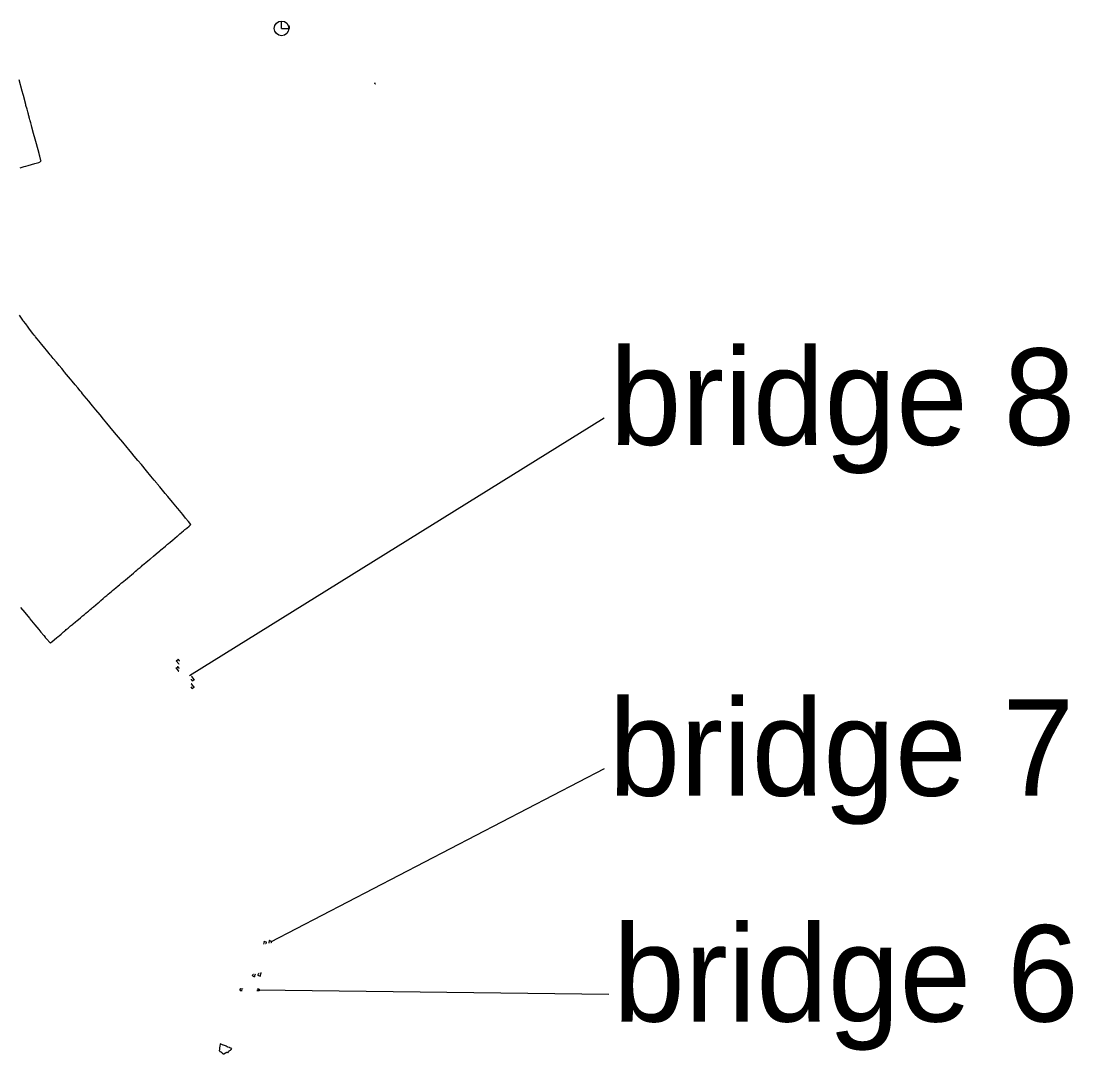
# Model space of a CAD drawing. Extents: x 620961 to 671816, y 407040 to 436930.
# Drawn here: x 648401 to 671816, y 407040 to 430021 of the extents above; entities that cross this region are included whole.
import ezdxf

# ---------------------------------------------------------------- set-up
doc = ezdxf.new("R2010")
doc.units = 0
for name, color, linetype in [('R_Lighting_Poles', 7, 'Continuous'), ('R_No Plot', 7, 'Continuous'), ('T_Lighting_Boxes', 7, 'Continuous'), ('T_Lighting_Conduit', 7, 'Continuous')]:
    doc.layers.add(name, color=color, linetype=linetype)

msp = doc.modelspace()

# ---------------------------------------------------------------- linework, layer by layer
at = {"layer": 'R_Lighting_Poles'}
for p, q in [((656273, 428641), (656271, 428643)), ((656279, 428634), (656273, 428641)), ((656274, 428636), (656273, 428634)), ((656274, 428636), (656278, 428639)), ((656278, 428639), (656280, 428641)), ((656288, 428625), (656279, 428634))]:
    msp.add_line(p, q, dxfattribs=at)
msp.add_circle((656289, 428623), 2.4, dxfattribs=at)
for centre, radius, start, end in [((656274, 428640), 1.27, 92.9915, 132.6308), ((656274, 428640), 1.27, 132.6308, 172.2701), ((656276, 428640), 3.45, 172.2701, 196.0657), ((656278, 428640), 5.94, 196.0657, 210.9299), ((656281, 428642), 9.57, 210.9299, 222.6308), ((656274, 428638), 3.45, 69.1958, 92.9915), ((656281, 428642), 9.57, 222.6308, 234.3317), ((656273, 428635), 5.94, 54.3317, 69.1958), ((656271, 428632), 9.57, 42.6308, 54.3317), ((656279, 428639), 5.94, 234.3317, 249.1958), ((656278, 428637), 3.45, 249.1958, 272.9915), ((656271, 428632), 9.57, 30.9299, 42.6308), ((656274, 428634), 5.94, 16.0657, 30.9299), ((656279, 428635), 1.27, 312.6308, 352.2701), ((656279, 428635), 1.27, 272.9915, 312.6308), ((656276, 428635), 3.45, 352.2701, 16.0657)]:
    msp.add_arc(centre, radius, start, end, dxfattribs=at)
at = {"layer": 'R_No Plot'}
for p, q in [((661381, 421189), (652154, 415453)), ((661381, 413383), (653955, 409528)), ((661482, 408359), (653677, 408462))]:
    msp.add_line(p, q, dxfattribs=at)
for points in [[(648378, 426758), (648469, 426782), (648506, 426793), (648561, 426809), (648710, 426848), (648798, 426872), (648845, 426906), (648843, 426920), (648818, 427013), (648818, 427013), (648818, 427013), (648810, 427040), (648810, 427040), (648810, 427040), (648802, 427071), (648802, 427072), (648802, 427072), (648780, 427152), (648780, 427152), (648780, 427152), (648765, 427207), (648744, 427286), (648715, 427391), (648681, 427518), (648641, 427662), (648632, 427694), (648616, 427755), (648603, 427804), (648602, 427809), (648598, 427823), (648591, 427849), (648588, 427859), (648585, 427871), (648582, 427883), (648581, 427887), (648574, 427913), (648568, 427935), (648568, 427936), (648568, 427936), (648566, 427941), (648563, 427953), (648560, 427964), (648556, 427980), (648552, 427994), (648550, 428000), (648541, 428032), (648534, 428059), (648510, 428144), (648505, 428164), (648452, 428363), (648452, 428364), (648452, 428364), (648445, 428388), (648445, 428388), (648445, 428389), (648424, 428464), (648357, 428712)], [(648389, 416974), (648484, 416861), (648586, 416736), (648600, 416719), (648711, 416587), (648798, 416482), (648843, 416426), (648909, 416348), (648936, 416316), (648941, 416309), (648974, 416271), (649040, 416192), (649053, 416185), (649054, 416184), (649092, 416216), (649192, 416298), (649228, 416329), (649246, 416344), (649291, 416382), (649346, 416428), (649365, 416444), (649369, 416447), (649379, 416456), (649390, 416464), (649408, 416480), (649427, 416496), (649449, 416515), (649463, 416526), (649480, 416541), (649505, 416562), (649544, 416595), (649562, 416610), (649615, 416655), (649650, 416684), (649678, 416708), (649723, 416745), (649768, 416784), (649803, 416812), (649843, 416847), (649879, 416876), (649900, 416895), (649939, 416927), (649966, 416951), (649994, 416974), (650015, 416991), (650114, 417074), (650138, 417095), (650177, 417131), (650226, 417173), (650267, 417207), (650311, 417242), (650338, 417267), (650380, 417301), (650415, 417330), (650439, 417349), (650514, 417414), (650565, 417455), (650593, 417479), (650639, 417519), (650675, 417547), (650690, 417561), (650724, 417589), (650768, 417626), (650822, 417671), (650859, 417702), (650902, 417738), (650927, 417759), (650950, 417779), (650980, 417804), (650995, 417817), (651011, 417830), (651053, 417866), (651068, 417878), (651079, 417887), (651107, 417912), (651144, 417942), (651180, 417972), (651188, 417979), (651250, 418031), (651267, 418045), (651273, 418051), (651281, 418058), (651349, 418115), (651410, 418169), (651491, 418234), (651507, 418248), (651553, 418286), (651570, 418300), (651614, 418338), (651631, 418353), (651649, 418367), (651662, 418379), (651685, 418398), (651719, 418426), (651811, 418503), (651822, 418513), (651878, 418560), (651888, 418568), (651898, 418577), (651936, 418609), (651967, 418636), (651982, 418649), (652018, 418679), (652050, 418706), (652071, 418723), (652090, 418739), (652141, 418783), (652173, 418809), (652181, 418823), (652131, 418884), (652064, 418964), (651999, 419044), (651891, 419174), (651881, 419186), (651769, 419320), (651669, 419440), (651608, 419513), (651520, 419622), (651488, 419659), (651432, 419727), (651421, 419740), (651366, 419806), (651291, 419896), (651195, 420011), (651080, 420152), (651003, 420244), (650922, 420342), (650870, 420404), (650803, 420485), (650762, 420535), (650663, 420652), (650570, 420766), (650529, 420816), (650446, 420914), (650314, 421074), (650238, 421164), (650160, 421260), (650069, 421369), (649994, 421460), (649964, 421495), (649907, 421564), (649808, 421684), (649771, 421728), (649743, 421762), (649719, 421790), (649663, 421858), (649603, 421929), (649536, 422011), (649500, 422056), (649371, 422211), (649361, 422224), (649306, 422290), (649248, 422359), (649189, 422430), (649119, 422515), (649095, 422544), (649072, 422572), (649049, 422598), (649025, 422627), (648967, 422698), (648930, 422742), (648861, 422824), (648827, 422867), (648802, 422898), (648751, 422960), (648725, 422993), (648713, 423008), (648692, 423034), (648657, 423078), (648574, 423185), (648558, 423208), (648504, 423281), (648459, 423342), (648444, 423362), (648440, 423367), (648410, 423408), (648365, 423474)]]:
    msp.add_lwpolyline(points, dxfattribs=at)
msp.add_lwpolyline([(652873, 407252), (652836, 407267), (652833, 407248), (652828, 407223), (652822, 407196), (652820, 407180), (652818, 407161), (652816, 407145), (652811, 407106), (652822, 407100), (652829, 407098), (652833, 407095), (652834, 407095), (652845, 407087), (652850, 407085), (652854, 407083), (652859, 407082), (652863, 407080), (652865, 407079), (652874, 407065), (652884, 407046), (652886, 407046), (652890, 407048), (652896, 407049), (652901, 407048), (652901, 407047), (652903, 407045), (652908, 407042), (652912, 407040), (652913, 407040), (652955, 407064), (652961, 407066), (652968, 407071), (652975, 407075), (652982, 407080), (652988, 407081), (652994, 407082), (652998, 407078), (653000, 407077), (653007, 407071), (653010, 407070), (653027, 407102), (653034, 407108), (653037, 407110), (653043, 407113), (653051, 407118), (653060, 407124), (653068, 407132), (653078, 407142), (653090, 407159), (653068, 407169), (653046, 407178), (653040, 407180), (653007, 407194), (652991, 407201), (652970, 407210), (652950, 407219), (652933, 407226), (652910, 407236), (652902, 407239)], close=True, dxfattribs=at)
at = {"layer": 'T_Lighting_Boxes'}
for p, q in [((651850, 415625), (651852, 415622)), ((651856, 415790), (651858, 415787)), ((651889, 415657), (651892, 415654)), ((651896, 415821), (651898, 415819)), ((652211, 415175), (652213, 415172)), ((652217, 415340), (652220, 415337)), ((652251, 415207), (652253, 415204)), ((652257, 415372), (652259, 415369)), ((653812, 409542), (653811, 409538)), ((653929, 409564), (653928, 409561)), ((653978, 409552), (653978, 409548)), ((653861, 409529), (653860, 409525)), ((653554, 408780), (653552, 408776)), ((653601, 408760), (653599, 408756)), ((653677, 408793), (653676, 408790)), ((653724, 408775), (653723, 408771)), ((653283, 408487), (653279, 408487)), ((653282, 408448), (653279, 408448)), ((653702, 408478), (653698, 408478)), ((653701, 408441), (653698, 408442))]:
    msp.add_line(p, q, dxfattribs=at)
for points in [[(651852, 415622), (651850, 415620), (651847, 415623), (651850, 415625)], [(651858, 415787), (651856, 415785), (651854, 415788), (651856, 415790)], [(651892, 415654), (651889, 415652), (651887, 415655), (651889, 415657)], [(651898, 415819), (651896, 415817), (651894, 415820), (651896, 415821)], [(652213, 415172), (652211, 415170), (652209, 415173), (652211, 415175)], [(652220, 415337), (652217, 415335), (652215, 415338), (652217, 415340)], [(652253, 415204), (652251, 415202), (652248, 415205), (652251, 415207)], [(652259, 415369), (652257, 415367), (652255, 415370), (652257, 415372)], [(653811, 409538), (653808, 409539), (653809, 409543), (653812, 409542)], [(653928, 409561), (653925, 409561), (653926, 409565), (653929, 409564)], [(653978, 409548), (653975, 409549), (653976, 409553), (653978, 409552)], [(653860, 409525), (653857, 409526), (653858, 409530), (653861, 409529)], [(653552, 408776), (653550, 408777), (653551, 408781), (653554, 408780)], [(653599, 408756), (653597, 408757), (653598, 408761), (653601, 408760)], [(653676, 408790), (653673, 408791), (653674, 408794), (653677, 408793)], [(653723, 408771), (653720, 408772), (653722, 408776), (653724, 408775)], [(653279, 408487), (653279, 408490), (653283, 408489), (653283, 408487)], [(653279, 408448), (653279, 408451), (653282, 408451), (653282, 408448)], [(653698, 408478), (653698, 408481), (653702, 408481), (653702, 408478)], [(653698, 408442), (653698, 408444), (653701, 408444), (653701, 408441)]]:
    msp.add_lwpolyline(points, dxfattribs=at)
for points in [[(651850, 415623), (651851, 415622), (651850, 415622), (651849, 415623), (651849, 415624)], [(651856, 415788), (651857, 415787), (651856, 415786), (651855, 415788), (651856, 415788)], [(651890, 415655), (651890, 415654), (651890, 415654), (651888, 415655), (651889, 415656)], [(651896, 415819), (651897, 415819), (651896, 415818), (651895, 415819), (651896, 415820)], [(652211, 415173), (652212, 415172), (652211, 415172), (652210, 415173), (652211, 415174)], [(652218, 415338), (652218, 415337), (652217, 415336), (652216, 415338), (652217, 415338)], [(652251, 415205), (652251, 415204), (652251, 415204), (652250, 415205), (652250, 415206)], [(652257, 415370), (652258, 415369), (652257, 415368), (652256, 415370), (652257, 415370)], [(653811, 409540), (653810, 409540), (653809, 409540), (653810, 409541), (653811, 409541)], [(653928, 409563), (653927, 409562), (653927, 409562), (653927, 409564), (653928, 409564)], [(653977, 409550), (653977, 409549), (653976, 409550), (653976, 409551), (653977, 409551)], [(653860, 409527), (653860, 409526), (653859, 409527), (653859, 409528), (653860, 409528)], [(653552, 408778), (653552, 408778), (653551, 408778), (653552, 408780), (653552, 408779)], [(653599, 408759), (653599, 408758), (653598, 408758), (653598, 408760), (653599, 408759)], [(653675, 408792), (653675, 408791), (653674, 408792), (653675, 408793), (653676, 408793)], [(653723, 408773), (653722, 408772), (653722, 408773), (653722, 408774), (653723, 408774)], [(653281, 408488), (653280, 408488), (653280, 408489), (653282, 408489), (653282, 408488)], [(653281, 408449), (653280, 408449), (653280, 408450), (653281, 408450), (653281, 408449)], [(653700, 408479), (653699, 408479), (653699, 408480), (653701, 408480), (653701, 408479)], [(653699, 408443), (653699, 408443), (653699, 408443), (653700, 408443), (653700, 408443)]]:
    msp.add_lwpolyline(points, close=True, dxfattribs=at)
at = {"layer": 'T_Lighting_Conduit'}
for p, q in [((654200, 429858), (654200, 430021)), ((654365, 429913), (654380, 429913)), ((654200, 429858), (654380, 429858)), ((654380, 429858), (654380, 429898)), ((651850, 415623), (651889, 415654)), ((651850, 415622), (651904, 415555)), ((651856, 415788), (651895, 415819)), ((651857, 415787), (651910, 415721)), ((651890, 415654), (651916, 415622)), ((651896, 415818), (651922, 415786)), ((651910, 415721), (651917, 415718)), ((651916, 415622), (651915, 415616)), ((651922, 415786), (651921, 415781)), ((651904, 415555), (651910, 415554)), ((652203, 415437), (652197, 415438)), ((652256, 415370), (652203, 415437)), ((652185, 415205), (652186, 415211)), ((652210, 415173), (652185, 415205)), ((652197, 415272), (652190, 415273)), ((652192, 415369), (652192, 415375)), ((652217, 415338), (652192, 415369)), ((652250, 415205), (652197, 415272)), ((652211, 415173), (652250, 415204)), ((652218, 415338), (652257, 415369)), ((653810, 409540), (653796, 409486)), ((653859, 409528), (653811, 409540)), ((653927, 409562), (653914, 409511)), ((653928, 409563), (653976, 409550)), ((653976, 409550), (653968, 409515)), ((653796, 409486), (653798, 409481)), ((653849, 409492), (653845, 409490)), ((653859, 409527), (653849, 409492)), ((653914, 409511), (653917, 409506)), ((653968, 409515), (653963, 409514)), ((653675, 408793), (653693, 408839)), ((653693, 408839), (653699, 408841)), ((653723, 408774), (653749, 408843)), ((653749, 408843), (653748, 408850)), ((653552, 408779), (653566, 408813)), ((653552, 408778), (653598, 408759)), ((653566, 408813), (653572, 408815)), ((653599, 408760), (653623, 408820)), ((653623, 408820), (653622, 408824)), ((653675, 408792), (653722, 408774)), ((653281, 408450), (653281, 408488)), ((653281, 408449), (653318, 408449)), ((653282, 408488), (653328, 408487)), ((653318, 408449), (653322, 408453)), ((653328, 408487), (653334, 408483)), ((653650, 408444), (653646, 408447)), ((653699, 408443), (653650, 408444)), ((653664, 408481), (653658, 408477)), ((653699, 408480), (653664, 408481)), ((653700, 408479), (653699, 408443))]:
    msp.add_line(p, q, dxfattribs=at)
msp.add_circle((654200, 429858), 163, dxfattribs=at)

# ---------------------------------------------------------------- texts
at = {"layer": 'R_No Plot'}
for s, p in [('bridge 8', (661504, 420591)), ('bridge 7', (661478, 412785)), ('bridge 6', (661580, 407761))]:
    msp.add_text(s, height=2144.3, dxfattribs=at).set_placement(p)

doc.saveas('drawing.dxf')
